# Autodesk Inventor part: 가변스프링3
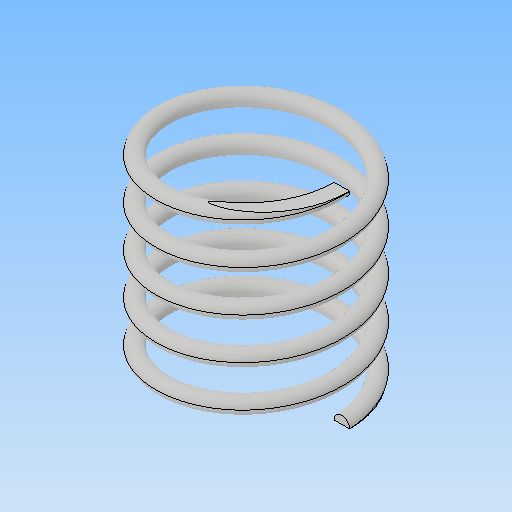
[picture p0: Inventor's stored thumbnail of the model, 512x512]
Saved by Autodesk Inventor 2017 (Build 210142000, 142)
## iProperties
Part Number: 가변스프링3
Material: 일반
Document SubType Name: Modeling
Designer: MRC
Density: 1 g/cm^3
Appearance: 기본값
Mass: 1.06846 g
Surface Area: 21.6623 cm^2
Volume: 1.06846 cm^3
Author: MRC
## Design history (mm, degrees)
sketch "스케치1"
  geometry: L1 (0, 0)-(0, 26.358); L2 (0, 0)-(11, 0); L3 (0, 26.358)-(11, 26.358); C1 r 1 at (11, 0)
  constraints: 6 end point, 2 horizontal, 1 centre point, 1 coincident, 1 vertical
  dimensions: "d0" = 26.35829 distance of L1.start L1.end (derived); "d1" = 11 distance of L1.end L3.end; "d2" = 11 distance of L1.start L2.end; "d3" = 2 diameter of C1
feature "코일1" sketch "스케치1" pitch "d4" = 10; turns "d6" = 5; dims "d5" = 26.35831 (computed from d0), "d7" = 0, angle "d8" = 90 deg, angle "d9" = 90 deg, "d10" = 0, "d11" = 0
sketch "스케치2"
  geometry: L1 (26.358, 15)-(0, 15); L2 (0, 15)-(0, -15); L3 (0, -15)-(26.358, -15); L4 (26.358, -15)-(26.358, 15); 2 further points
  constraints: 8 end point, 2 parallel, 1 coincident, 1 horizontal, 1 midpoint, 1 perpendicular
  dimensions: "d12" = 26.35831 distance of L2.end L3.end (computed from d0); "d13" = 30 distance of L3.end L1.start
extrude "돌출1" sketch "스케치2" stored distance "d14" = 0; taper "d15" = 0 deg
node "솔리드1"
